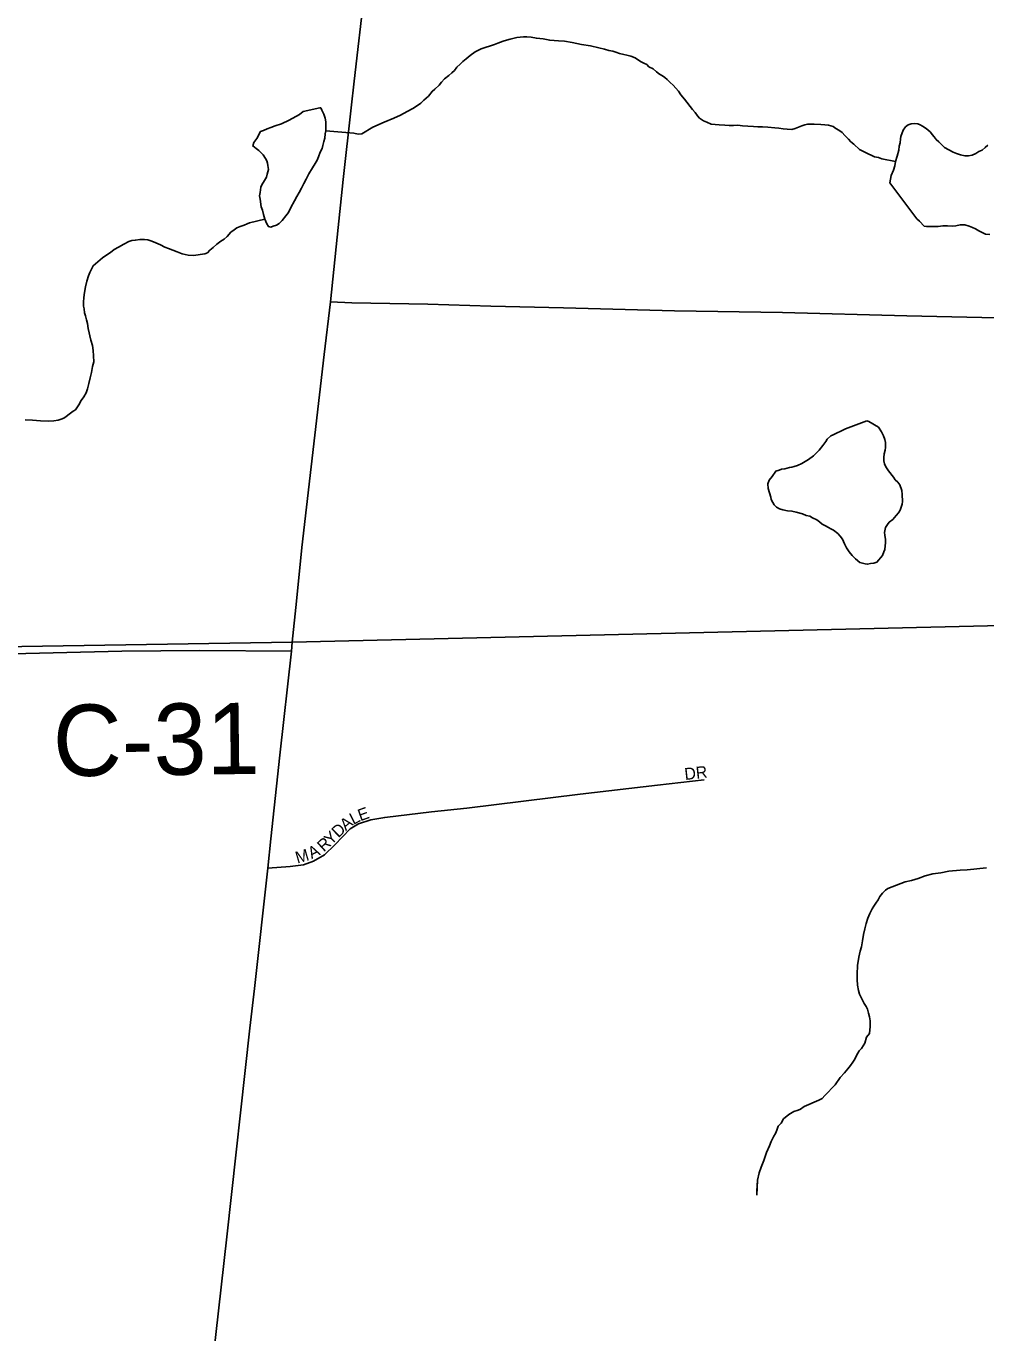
# Model space of a CAD drawing. Extents: x 10.6 to 44.6, y -2.6 to 23.4.
# Drawn here: x 14.036 to 14.801, y 20.288 to 21.329 of the extents above; entities that cross this region are included whole.
import ezdxf

# ---------------------------------------------------------------- set-up
doc = ezdxf.new("R2010")
doc.units = 0
for name, color, linetype in [('GM_X_County_Road', 7, 'Continuous'), ('GM_X_County_Road_Text', 7, 'Continuous'), ('GM_X_Minor_Lake', 7, 'Continuous'), ('GM_X_Minor_River', 7, 'Continuous'), ('GM_X_State_Route', 7, 'Continuous'), ('GM_X_Township', 7, 'Continuous'), ('GM_X_Township_Road', 7, 'Continuous'), ('GM_X_Township_Subdivision', 7, 'Continuous'), ('GM_X_Township_Subdivision_Text', 7, 'Continuous')]:
    doc.layers.add(name, color=color, linetype=linetype)

msp = doc.modelspace()

# ---------------------------------------------------------------- linework, layer by layer
at = {"layer": 'GM_X_County_Road'}
msp.add_lwpolyline([(14.2475, 20.8313), (14.1744, 20.8318), (14.1122, 20.8315), (14.0027, 20.8286), (13.9311, 20.8276), (13.8425, 20.8249), (13.5799, 20.8207), (13.3897, 20.8177), (13.3171, 20.8165), (13.2335, 20.8153), (13.2033, 20.8149)], dxfattribs=at)
at = {"layer": 'GM_X_Minor_Lake'}
for points in [[(14.2568, 21.2612), (14.2538, 21.259), (14.2456, 21.2543), (14.2395, 21.2515), (14.2346, 21.2499), (14.2312, 21.2486), (14.2282, 21.2474), (14.2252, 21.2462), (14.2229, 21.2454), (14.22, 21.2397), (14.2174, 21.2366), (14.2167, 21.2339), (14.2194, 21.2317), (14.2214, 21.2302), (14.2249, 21.2268), (14.2268, 21.2238), (14.228, 21.222), (14.2284, 21.2201), (14.2288, 21.2182), (14.2293, 21.2152), (14.2282, 21.2113), (14.2275, 21.209), (14.2261, 21.2063), (14.2239, 21.2029), (14.2231, 21.201), (14.2225, 21.1968), (14.2221, 21.1941), (14.2226, 21.1915), (14.2235, 21.1854), (14.2243, 21.1827), (14.2251, 21.1793), (14.2263, 21.1756), (14.2279, 21.1718), (14.2291, 21.1696), (14.231, 21.1692), (14.2329, 21.17), (14.2356, 21.1708), (14.2378, 21.172), (14.2401, 21.1744), (14.243, 21.1782), (14.2452, 21.1809), (14.2471, 21.1848), (14.25, 21.1901), (14.2518, 21.1936), (14.2537, 21.1967), (14.2555, 21.2001), (14.2573, 21.204), (14.2591, 21.2074), (14.2613, 21.2117), (14.2643, 21.2163), (14.2665, 21.2198), (14.2679, 21.2225), (14.269, 21.2251), (14.2705, 21.229), (14.2719, 21.2317), (14.2726, 21.2343), (14.2733, 21.2374), (14.274, 21.2401), (14.2743, 21.2435), (14.275, 21.2458), (14.275, 21.2477), (14.2749, 21.2503), (14.2749, 21.253), (14.2744, 21.256), (14.2732, 21.2591), (14.2716, 21.2624), (14.2708, 21.2643), (14.2701, 21.2643)], [(14.2701, 21.2643), (14.2568, 21.2612)], [(14.8025, 21.2345), (14.8003, 21.2325), (14.798, 21.2306), (14.7954, 21.2294), (14.7928, 21.2278), (14.7901, 21.2266), (14.7871, 21.2261), (14.7841, 21.2261), (14.7806, 21.2268), (14.7776, 21.2278), (14.7749, 21.2289), (14.768, 21.2326), (14.766, 21.2344), (14.7633, 21.237), (14.7613, 21.2389), (14.7598, 21.2411), (14.7582, 21.243), (14.7567, 21.2449), (14.7547, 21.2467), (14.7524, 21.2482), (14.7505, 21.2497), (14.7485, 21.2508), (14.7466, 21.2515), (14.7443, 21.2518), (14.7413, 21.2514), (14.739, 21.2506), (14.7368, 21.249), (14.7349, 21.2463), (14.7331, 21.2413), (14.7328, 21.2394), (14.7325, 21.2364), (14.7318, 21.2337), (14.7315, 21.2306), (14.7301, 21.2257), (14.729, 21.2215), (14.7283, 21.218), (14.7273, 21.2146), (14.7254, 21.2104), (14.7244, 21.2046)], [(14.7244, 21.2046), (14.746, 21.1759), (14.7479, 21.174), (14.7518, 21.1699), (14.7537, 21.1696), (14.7583, 21.1697), (14.7628, 21.1698), (14.7666, 21.1702), (14.7704, 21.1703), (14.7742, 21.17), (14.7769, 21.1701), (14.7803, 21.1709), (14.7822, 21.1709), (14.7841, 21.171), (14.7875, 21.1699), (14.7902, 21.1688), (14.7925, 21.1678), (14.7952, 21.1663), (14.7979, 21.1648), (14.8006, 21.1637)], [(14.8006, 21.1637), (14.804, 21.1634)], [(14.706, 21.015), (14.6891, 21.0086), (14.6853, 21.0066), (14.6819, 21.005), (14.6793, 21.0038), (14.6774, 21.003), (14.6744, 21.0003), (14.6733, 20.9983), (14.6711, 20.9953), (14.6681, 20.9914), (14.6636, 20.9871), (14.6595, 20.984), (14.6543, 20.9808), (14.6509, 20.9792), (14.6482, 20.9784), (14.6463, 20.978), (14.6444, 20.9776), (14.6407, 20.9767), (14.638, 20.9763), (14.6361, 20.9755), (14.6335, 20.9747), (14.6305, 20.9704), (14.6283, 20.9677), (14.6272, 20.9647), (14.6273, 20.9609), (14.6294, 20.9541), (14.6298, 20.9522), (14.631, 20.9499), (14.6321, 20.948), (14.6341, 20.9462), (14.6364, 20.9447), (14.6391, 20.944), (14.6429, 20.9433), (14.6463, 20.943), (14.6498, 20.942), (14.6547, 20.9409), (14.6578, 20.9395), (14.6605, 20.9388), (14.6628, 20.9377), (14.6663, 20.9359), (14.6682, 20.9344), (14.6705, 20.9325), (14.6732, 20.9311), (14.6755, 20.93), (14.6774, 20.9289), (14.6794, 20.9278), (14.6828, 20.9252), (14.6848, 20.923), (14.6867, 20.9207), (14.6883, 20.917), (14.6899, 20.9136), (14.6919, 20.9106), (14.6943, 20.9076), (14.697, 20.905), (14.7005, 20.902), (14.7047, 20.901), (14.7066, 20.9006), (14.7089, 20.9011), (14.7115, 20.9015), (14.7141, 20.9023), (14.7186, 20.9077), (14.7197, 20.9104), (14.7204, 20.9123), (14.7207, 20.9154), (14.721, 20.9177), (14.721, 20.9203), (14.7205, 20.9237), (14.7201, 20.926), (14.7208, 20.9298), (14.7226, 20.9322), (14.7237, 20.9341), (14.7267, 20.9364), (14.7293, 20.9395), (14.7312, 20.9415), (14.7327, 20.9438), (14.7334, 20.9461), (14.7341, 20.9484), (14.7344, 20.9506), (14.7343, 20.9563), (14.7339, 20.9594), (14.7322, 20.9639), (14.7307, 20.9661), (14.7287, 20.968), (14.7272, 20.9699), (14.7232, 20.9751), (14.7213, 20.9781), (14.7201, 20.9807), (14.7197, 20.983), (14.7196, 20.9857), (14.7199, 20.9887), (14.7206, 20.9914), (14.7209, 20.9937), (14.7209, 20.9956), (14.7209, 20.9975), (14.7204, 21.0001), (14.7192, 21.0028), (14.7176, 21.0061), (14.7153, 21.0099)], [(14.7153, 21.0099), (14.7076, 21.0143), (14.7068, 21.0146), (14.706, 21.015)]]:
    msp.add_lwpolyline(points, dxfattribs=at)
at = {"layer": 'GM_X_Minor_River'}
for points in [[(14.275, 21.2458), (14.2971, 21.244), (14.3006, 21.2433), (14.3036, 21.2434), (14.3123, 21.2489), (14.3213, 21.2529), (14.3292, 21.2561), (14.3345, 21.2585), (14.3398, 21.2613), (14.3443, 21.2636), (14.348, 21.266), (14.3507, 21.268), (14.3529, 21.2703), (14.3566, 21.2734), (14.3596, 21.2773), (14.3618, 21.2792), (14.3652, 21.2823), (14.367, 21.2846), (14.3696, 21.2874), (14.373, 21.2901), (14.3752, 21.292), (14.3775, 21.294), (14.3793, 21.2967), (14.3819, 21.299), (14.3842, 21.301), (14.3868, 21.3033), (14.3898, 21.306), (14.3939, 21.3088), (14.3988, 21.3112), (14.4094, 21.3148), (14.412, 21.3156), (14.4162, 21.3173), (14.4188, 21.3181), (14.4218, 21.3189), (14.4249, 21.3197), (14.4271, 21.3202), (14.4298, 21.3206), (14.4325, 21.3207), (14.4351, 21.3207), (14.4385, 21.3204), (14.4427, 21.3197), (14.4481, 21.3191), (14.4534, 21.3181), (14.4603, 21.3175), (14.4652, 21.3172), (14.4713, 21.3162), (14.4786, 21.3148), (14.4859, 21.3135), (14.4924, 21.3121), (14.4969, 21.311), (14.5004, 21.31), (14.5035, 21.3093), (14.5061, 21.3086), (14.5088, 21.3075), (14.5123, 21.3068), (14.5149, 21.3061), (14.518, 21.3054), (14.5214, 21.304), (14.5257, 21.301), (14.5284, 21.2999), (14.5307, 21.2988), (14.5322, 21.297), (14.5357, 21.2952), (14.5384, 21.2929), (14.5407, 21.2911), (14.5431, 21.2896), (14.545, 21.2885), (14.5469, 21.2867), (14.5493, 21.2844), (14.5516, 21.2822), (14.5539, 21.28), (14.5559, 21.2774), (14.5578, 21.2747), (14.5606, 21.271), (14.5672, 21.2628), (14.5692, 21.2605), (14.5711, 21.2579), (14.5727, 21.2561), (14.5758, 21.2539), (14.5785, 21.2528), (14.5819, 21.2513), (14.5884, 21.2507), (14.593, 21.2504), (14.5964, 21.2501), (14.5998, 21.2502), (14.6032, 21.2503), (14.607, 21.25), (14.6112, 21.2497), (14.6158, 21.2494), (14.6192, 21.2491), (14.623, 21.2492), (14.6272, 21.2489), (14.6326, 21.2482), (14.636, 21.2479), (14.6394, 21.2476), (14.6425, 21.2473), (14.6463, 21.247), (14.6489, 21.2478), (14.6516, 21.2487), (14.6542, 21.2499), (14.6565, 21.2507)], [(14.6565, 21.2507), (14.6588, 21.2511), (14.6641, 21.2512), (14.6694, 21.2509), (14.6725, 21.2506), (14.6755, 21.2503), (14.6774, 21.25), (14.6793, 21.2493), (14.6813, 21.2478), (14.6836, 21.2463), (14.6863, 21.2445), (14.6886, 21.2422), (14.6913, 21.2393), (14.6933, 21.237), (14.6956, 21.2352), (14.7003, 21.2311), (14.7049, 21.2285), (14.7122, 21.2253), (14.7152, 21.2246), (14.7179, 21.2235), (14.729, 21.2215)], [(14.0354, 21.0156), (14.0411, 21.0154), (14.0476, 21.0148), (14.0537, 21.0145), (14.0582, 21.015), (14.0616, 21.0154), (14.0639, 21.0162), (14.0662, 21.0171), (14.068, 21.0182), (14.0703, 21.0202), (14.0736, 21.0225), (14.0755, 21.0237), (14.0781, 21.0276), (14.0799, 21.031), (14.0821, 21.0341), (14.084, 21.0372), (14.0851, 21.0403), (14.0861, 21.0445), (14.0872, 21.0491), (14.0882, 21.0533), (14.0889, 21.0582), (14.0899, 21.062), (14.0898, 21.0666), (14.0894, 21.0708), (14.0889, 21.0749), (14.0877, 21.0791), (14.0855, 21.0885), (14.0851, 21.0923), (14.0843, 21.0953), (14.0834, 21.0984), (14.0826, 21.101), (14.0822, 21.104), (14.0817, 21.1063), (14.0817, 21.1094), (14.082, 21.1132), (14.0827, 21.117), (14.0833, 21.1215), (14.0844, 21.1261), (14.0858, 21.1303), (14.0869, 21.133), (14.0894, 21.1384), (14.0932, 21.1415), (14.0969, 21.1446), (14.1003, 21.147), (14.1033, 21.149), (14.1063, 21.1513), (14.1096, 21.1533), (14.1138, 21.1556), (14.1179, 21.1576), (14.1202, 21.1584), (14.1232, 21.1589), (14.1266, 21.1593), (14.1304, 21.1594), (14.1331, 21.1591), (14.1362, 21.158), (14.1393, 21.1566), (14.1431, 21.1551), (14.1465, 21.1533), (14.1496, 21.1522), (14.1531, 21.1508), (14.1565, 21.1494), (14.1604, 21.1479), (14.1653, 21.1469), (14.1695, 21.1466), (14.1786, 21.1479), (14.1805, 21.1487), (14.1824, 21.1507), (14.185, 21.153), (14.188, 21.1557), (14.1913, 21.1581), (14.194, 21.1597), (14.1962, 21.1616), (14.1992, 21.1651), (14.2018, 21.1671), (14.204, 21.1686), (14.2067, 21.1698), (14.2097, 21.1707), (14.2123, 21.1719), (14.2142, 21.1727), (14.2263, 21.1756)], [(14.6184, 20.3979), (14.6189, 20.41), (14.6183, 20.4013), (14.6189, 20.41), (14.6203, 20.4158), (14.6217, 20.4204), (14.6239, 20.4257), (14.6261, 20.4319), (14.6286, 20.4372), (14.6297, 20.4407), (14.6319, 20.4449), (14.6333, 20.4472), (14.6344, 20.4499), (14.6355, 20.453), (14.6377, 20.4553), (14.6396, 20.4588), (14.644, 20.4623), (14.6478, 20.4646), (14.6512, 20.4658), (14.6531, 20.4666), (14.6561, 20.4686), (14.6599, 20.4702), (14.664, 20.4722), (14.6678, 20.4738), (14.6704, 20.475), (14.6726, 20.4773), (14.6808, 20.4859), (14.6849, 20.4917), (14.6882, 20.4955), (14.6908, 20.4986), (14.693, 20.5013), (14.6949, 20.504), (14.6964, 20.5064), (14.6978, 20.5094), (14.7, 20.5129), (14.7019, 20.5148), (14.7045, 20.5191), (14.7059, 20.524), (14.7081, 20.5267), (14.7087, 20.5325), (14.7086, 20.537), (14.7082, 20.54), (14.7074, 20.5431), (14.7065, 20.5461), (14.7054, 20.5483), (14.7038, 20.5506), (14.7022, 20.554), (14.7002, 20.5581), (14.6994, 20.5611), (14.6985, 20.5653), (14.6984, 20.5699), (14.6983, 20.574), (14.6986, 20.5809), (14.6996, 20.5877), (14.7006, 20.5923), (14.7017, 20.5958), (14.7027, 20.6007), (14.7034, 20.6057), (14.7044, 20.6103), (14.7055, 20.6145), (14.7069, 20.6187), (14.7083, 20.6225), (14.7102, 20.626), (14.7116, 20.6283), (14.7131, 20.6306), (14.715, 20.6333), (14.7164, 20.636), (14.7186, 20.6387), (14.7209, 20.641), (14.7227, 20.6422), (14.7367, 20.6475), (14.7416, 20.6487), (14.7469, 20.6503), (14.7526, 20.6524), (14.7586, 20.654), (14.7651, 20.6549), (14.7715, 20.6562), (14.7803, 20.6568), (14.786, 20.6573), (14.7913, 20.6578), (14.7962, 20.6583), (14.8015, 20.6587)]]:
    msp.add_lwpolyline(points, dxfattribs=at)
at = {"layer": 'GM_X_State_Route'}
for points in [[(14.295, 21.2643), (14.2974, 21.2855), (14.3057, 21.3568), (14.3154, 21.4433), (14.3156, 21.4453)], [(14.2839, 21.1613), (14.2887, 21.2072), (14.295, 21.2643)], [(14.1848, 20.2658), (14.1959, 20.3647), (14.2143, 20.5311), (14.218, 20.5626), (14.2286, 20.6585), (14.231, 20.6819), (14.2382, 20.7486), (14.2475, 20.8313), (14.2482, 20.8385), (14.2515, 20.8711), (14.2559, 20.914), (14.2737, 21.0676), (14.2785, 21.1098), (14.2839, 21.1613)]]:
    msp.add_lwpolyline(points, dxfattribs=at)
at = {"layer": 'GM_X_Township'}
for points in [[(13.2033, 20.8217), (14.2481, 20.8385), (14.8927, 20.8536), (15.2545, 20.8646), (15.2514, 21.0808), (15.2493, 21.2218), (15.2389, 21.9444), (15.2375, 22.264), (15.2363, 22.3267)], [(15.2709, 19.5646), (15.2685, 20.051), (15.2587, 20.5958), (15.2545, 20.8646), (14.8927, 20.8536), (14.2481, 20.8385), (13.2033, 20.8217)]]:
    msp.add_lwpolyline(points, dxfattribs=at)
at = {"layer": 'GM_X_Township_Road'}
msp.add_lwpolyline([(15.2514, 21.0808), (15.2417, 21.0821), (15.2229, 21.0832), (15.2006, 21.0845), (15.1667, 21.0859), (15.107, 21.088), (15.0511, 21.0896), (14.9957, 21.0912), (14.8873, 21.0955), (14.8548, 21.0961), (14.8096, 21.0969), (14.7378, 21.0986), (14.6389, 21.1012), (14.5528, 21.1025), (14.4643, 21.105), (14.4065, 21.1063), (14.3562, 21.1079), (14.2957, 21.109), (14.2785, 21.1098)], dxfattribs=at)
at = {"layer": 'GM_X_Township_Subdivision'}
msp.add_lwpolyline([(14.2286, 20.6585), (14.2465, 20.6598), (14.2571, 20.6612), (14.2652, 20.6642), (14.2739, 20.6691), (14.2822, 20.6772), (14.2943, 20.6898), (14.3009, 20.6937), (14.3108, 20.6969), (14.3218, 20.6989), (14.3592, 20.7033), (14.3873, 20.7063), (14.4776, 20.7174), (14.5391, 20.7247), (14.5763, 20.7289)], dxfattribs=at)

# ---------------------------------------------------------------- texts
at = {"layer": 'GM_X_County_Road_Text'}
msp.add_text('C-31', height=0.05682, rotation=0.6714, dxfattribs=at).set_placement((14.0577, 20.7317))
at = {"layer": 'GM_X_Township_Subdivision_Text'}
for s, rotation, p in [('DR', 6.3375, (14.5612, 20.7287)), ('E', 19.8174, (14.3024, 20.6958)), ('A', 39.3186, (14.2908, 20.6879)), ('L', 27.3959, (14.2968, 20.6929)), ('Y', 44.5691, (14.2791, 20.6763)), ('D', 44.5209, (14.285, 20.6822)), ('A', 27.3306, (14.2636, 20.6656)), ('R', 42.3164, (14.2733, 20.671)), ('M', 16.2456, (14.2522, 20.6621))]:
    msp.add_text(s, height=0.00947, rotation=rotation, dxfattribs=at).set_placement(p)

doc.saveas('drawing.dxf')
